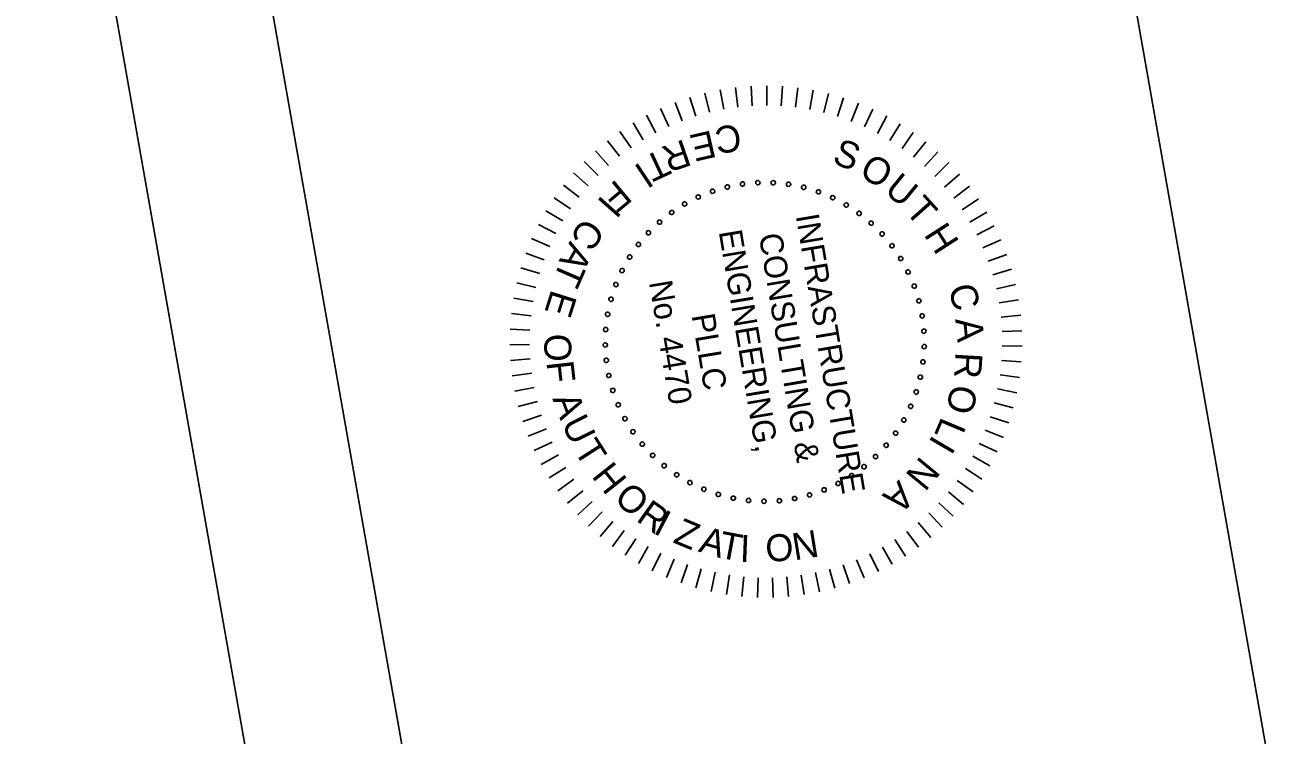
# Model space of a CAD drawing. Extents: x 1971280 to 1971503, y 796034 to 796348.
# Drawn here: x 1971311.8 to 1971344.03, y 796102.52 to 796120.9 of the extents above; entities that cross this region are included whole.
import ezdxf

# ---------------------------------------------------------------- set-up
doc = ezdxf.new("R2010")
doc.units = 0
for name, color, linetype in [('BR_BORDER LINES', 7, 'Continuous'), ('BR_TEXT', 7, 'Continuous'), ('Level 31', 7, 'Continuous')]:
    doc.layers.add(name, color=color, linetype=linetype)

msp = doc.modelspace()

# ---------------------------------------------------------------- linework, layer by layer
at = {"layer": 'BR_BORDER LINES'}
for p, q in [((1971286.058, 796303.806), (1971332.766, 796038.559)), ((1971336.584, 796143.739), (1971344.027, 796101.468))]:
    msp.add_line(p, q, dxfattribs=at)
at = {"layer": 'BR_TEXT'}
for p, q in [((1971330.985, 796119.326), (1971330.985, 796118.816)), ((1971328.996, 796119.026), (1971329.148, 796118.54)), ((1971329.385, 796119.134), (1971329.507, 796118.64)), ((1971329.78, 796119.219), (1971329.872, 796118.718)), ((1971330.179, 796119.279), (1971330.241, 796118.773)), ((1971330.582, 796119.314), (1971330.612, 796118.806)), ((1971331.389, 796119.312), (1971331.357, 796118.804)), ((1971331.791, 796119.274), (1971331.728, 796118.769)), ((1971332.19, 796119.212), (1971332.097, 796118.711)), ((1971332.585, 796119.125), (1971332.461, 796118.631)), ((1971332.973, 796119.014), (1971332.819, 796118.529)), ((1971328.241, 796118.739), (1971328.452, 796118.275)), ((1971328.614, 796118.894), (1971328.796, 796118.418)), ((1971333.354, 796118.88), (1971333.171, 796118.405)), ((1971333.726, 796118.723), (1971333.514, 796118.26)), ((1971327.527, 796118.363), (1971327.792, 796117.928)), ((1971327.879, 796118.562), (1971328.117, 796118.111)), ((1971334.088, 796118.544), (1971333.848, 796118.094)), ((1971327.189, 796118.142), (1971327.48, 796117.724)), ((1971334.438, 796118.342), (1971334.172, 796117.908)), ((1971334.775, 796118.12), (1971334.483, 796117.703)), ((1971326.864, 796117.902), (1971327.18, 796117.503)), ((1971335.099, 796117.878), (1971334.781, 796117.48)), ((1971326.555, 796117.642), (1971326.895, 796117.263)), ((1971335.406, 796117.616), (1971335.065, 796117.238)), ((1971325.987, 796117.069), (1971326.37, 796116.733)), ((1971326.262, 796117.364), (1971326.624, 796117.006)), ((1971335.697, 796117.337), (1971335.334, 796116.98)), ((1971325.73, 796116.757), (1971326.133, 796116.446)), ((1971335.971, 796117.039), (1971335.586, 796116.706)), ((1971325.492, 796116.43), (1971325.914, 796116.144)), ((1971336.226, 796116.726), (1971335.822, 796116.416)), ((1971336.462, 796116.398), (1971336.039, 796116.113)), ((1971325.275, 796116.09), (1971325.713, 796115.83)), ((1971336.677, 796116.056), (1971336.238, 796115.798)), ((1971325.08, 796115.736), (1971325.533, 796115.504)), ((1971336.87, 796115.702), (1971336.416, 796115.471)), ((1971324.906, 796115.372), (1971325.372, 796115.167)), ((1971337.042, 796115.336), (1971336.575, 796115.133)), ((1971324.754, 796114.997), (1971325.232, 796114.822)), ((1971337.191, 796114.961), (1971336.713, 796114.787)), ((1971324.626, 796114.615), (1971325.114, 796114.468)), ((1971337.317, 796114.577), (1971336.829, 796114.433)), ((1971324.521, 796114.224), (1971325.017, 796114.108)), ((1971337.42, 796114.187), (1971336.923, 796114.072)), ((1971324.441, 796113.829), (1971324.943, 796113.743)), ((1971337.498, 796113.79), (1971336.996, 796113.706)), ((1971324.384, 796113.429), (1971324.891, 796113.374)), ((1971337.552, 796113.39), (1971337.046, 796113.337)), ((1971324.352, 796113.026), (1971324.861, 796113.002)), ((1971337.582, 796112.987), (1971337.073, 796112.965)), ((1971324.345, 796112.622), (1971324.854, 796112.629)), ((1971337.587, 796112.584), (1971337.077, 796112.592)), ((1971324.362, 796112.219), (1971324.87, 796112.257)), ((1971337.567, 796112.18), (1971337.059, 796112.22)), ((1971324.404, 796111.817), (1971324.909, 796111.886)), ((1971337.523, 796111.779), (1971337.018, 796111.849)), ((1971324.47, 796111.419), (1971324.97, 796111.518)), ((1971337.454, 796111.381), (1971336.955, 796111.482)), ((1971324.561, 796111.025), (1971325.053, 796111.155)), ((1971337.361, 796110.988), (1971336.869, 796111.119)), ((1971324.675, 796110.638), (1971325.159, 796110.797)), ((1971337.245, 796110.601), (1971336.762, 796110.762)), ((1971324.813, 796110.258), (1971325.286, 796110.447)), ((1971337.105, 796110.222), (1971336.633, 796110.412)), ((1971324.973, 796109.888), (1971325.434, 796110.105)), ((1971336.942, 796109.853), (1971336.482, 796110.071)), ((1971325.156, 796109.527), (1971325.603, 796109.772)), ((1971336.757, 796109.493), (1971336.312, 796109.74)), ((1971325.361, 796109.179), (1971325.791, 796109.451)), ((1971336.551, 796109.146), (1971336.121, 796109.42)), ((1971325.586, 796108.844), (1971325.999, 796109.141)), ((1971336.324, 796108.813), (1971335.911, 796109.111)), ((1971325.831, 796108.523), (1971326.226, 796108.845)), ((1971336.076, 796108.493), (1971335.683, 796108.817)), ((1971326.096, 796108.218), (1971326.47, 796108.563)), ((1971335.81, 796108.189), (1971335.437, 796108.536)), ((1971326.378, 796107.929), (1971326.731, 796108.297)), ((1971326.678, 796107.659), (1971327.007, 796108.047)), ((1971335.526, 796107.903), (1971335.175, 796108.271)), ((1971326.993, 796107.406), (1971327.298, 796107.814)), ((1971334.908, 796107.383), (1971334.604, 796107.792)), ((1971335.225, 796107.633), (1971334.897, 796108.023)), ((1971327.324, 796107.174), (1971327.603, 796107.6)), ((1971327.668, 796106.962), (1971327.921, 796107.404)), ((1971334.576, 796107.153), (1971334.298, 796107.58)), ((1971328.024, 796106.772), (1971328.25, 796107.229)), ((1971333.874, 796106.755), (1971333.649, 796107.212)), ((1971334.231, 796106.943), (1971333.979, 796107.386)), ((1971328.391, 796106.604), (1971328.588, 796107.073)), ((1971328.768, 796106.458), (1971328.936, 796106.939)), ((1971329.152, 796106.336), (1971329.291, 796106.826)), ((1971332.742, 796106.325), (1971332.605, 796106.816)), ((1971333.128, 796106.445), (1971332.961, 796106.926)), ((1971333.506, 796106.589), (1971333.31, 796107.059)), ((1971329.544, 796106.237), (1971329.653, 796106.734)), ((1971329.941, 796106.162), (1971330.019, 796106.665)), ((1971330.342, 796106.112), (1971330.389, 796106.619)), ((1971330.745, 796106.086), (1971330.761, 796106.595)), ((1971331.149, 796106.085), (1971331.134, 796106.594)), ((1971331.552, 796106.108), (1971331.506, 796106.616)), ((1971331.953, 796106.156), (1971331.876, 796106.66)), ((1971332.35, 796106.229), (1971332.243, 796106.727))]:
    msp.add_line(p, q, dxfattribs=at)
for centre, start, end in [((1971329.967, 796116.708), 13.6677, 193.6677), ((1971330.358, 796116.783), 8.1292, 188.1292), ((1971330.358, 796116.783), 188.1292, 8.1292), ((1971330.755, 796116.819), 2.5907, 182.5907), ((1971330.755, 796116.819), 182.5907, 2.5907), ((1971331.154, 796116.817), 357.0523, 177.0523), ((1971331.154, 796116.817), 177.0523, 357.0523), ((1971331.55, 796116.776), 171.5138, 351.5138), ((1971331.55, 796116.776), 351.5138, 171.5138), ((1971331.941, 796116.698), 345.9753, 165.9753), ((1971329.214, 796116.447), 24.7446, 204.7446), ((1971329.214, 796116.447), 204.7446, 24.7446), ((1971329.584, 796116.596), 19.2061, 199.2061), ((1971329.584, 796116.596), 199.2061, 19.2061), ((1971329.967, 796116.708), 193.6677, 13.6677), ((1971331.941, 796116.698), 165.9753, 345.9753), ((1971332.323, 796116.582), 160.4369, 340.4369), ((1971332.323, 796116.582), 340.4369, 160.4369), ((1971332.691, 796116.43), 154.8984, 334.8984), ((1971332.691, 796116.43), 334.8984, 154.8984), ((1971328.526, 796116.047), 35.8215, 215.8215), ((1971328.86, 796116.264), 30.283, 210.283), ((1971328.86, 796116.264), 210.283, 30.283), ((1971333.043, 796116.243), 149.36, 329.36), ((1971333.043, 796116.243), 329.36, 149.36), ((1971328.214, 796115.799), 41.36, 221.36), ((1971328.214, 796115.799), 221.36, 41.36), ((1971328.526, 796116.047), 215.8215, 35.8215), ((1971333.375, 796116.022), 143.8215, 323.8215), ((1971333.375, 796116.022), 323.8215, 143.8215), ((1971333.685, 796115.771), 138.283, 318.283), ((1971333.685, 796115.771), 318.283, 138.283), ((1971327.927, 796115.522), 46.8984, 226.8984), ((1971327.927, 796115.522), 226.8984, 46.8984), ((1971333.969, 796115.491), 132.7446, 312.7446), ((1971333.969, 796115.491), 312.7446, 132.7446), ((1971327.668, 796115.219), 52.4369, 232.4369), ((1971327.668, 796115.219), 232.4369, 52.4369), ((1971334.224, 796115.185), 127.2061, 307.2061), ((1971334.224, 796115.185), 307.2061, 127.2061), ((1971327.44, 796114.892), 57.9753, 237.9753), ((1971327.44, 796114.892), 237.9753, 57.9753), ((1971334.449, 796114.856), 121.6677, 301.6677), ((1971334.449, 796114.856), 301.6677, 121.6677), ((1971327.245, 796114.544), 63.5138, 243.5138), ((1971327.245, 796114.544), 243.5138, 63.5138), ((1971334.641, 796114.507), 116.1292, 296.1292), ((1971334.641, 796114.507), 296.1292, 116.1292), ((1971327.084, 796114.18), 69.0523, 249.0523), ((1971327.084, 796114.18), 249.0523, 69.0523), ((1971334.798, 796114.14), 110.5907, 290.5907), ((1971334.798, 796114.14), 290.5907, 110.5907), ((1971326.958, 796113.801), 74.5907, 254.5907), ((1971326.958, 796113.801), 254.5907, 74.5907), ((1971334.92, 796113.761), 105.0523, 285.0523), ((1971334.92, 796113.761), 285.0523, 105.0523), ((1971326.87, 796113.412), 80.1292, 260.1292), ((1971326.87, 796113.412), 260.1292, 80.1292), ((1971335.004, 796113.371), 99.5138, 279.5138), ((1971335.004, 796113.371), 279.5138, 99.5138), ((1971326.82, 796113.017), 85.6677, 265.6677), ((1971326.82, 796113.017), 265.6677, 85.6677), ((1971335.05, 796112.975), 93.9753, 273.9753), ((1971335.05, 796112.975), 273.9753, 93.9753), ((1971326.809, 796112.619), 91.2061, 271.2061), ((1971326.809, 796112.619), 271.2061, 91.2061), ((1971335.057, 796112.576), 88.4369, 268.4369), ((1971335.057, 796112.576), 268.4369, 88.4369), ((1971326.836, 796112.221), 96.7446, 276.7446), ((1971326.836, 796112.221), 276.7446, 96.7446), ((1971335.026, 796112.179), 82.8984, 262.8984), ((1971335.026, 796112.179), 262.8984, 82.8984), ((1971326.901, 796111.827), 102.283, 282.283), ((1971326.901, 796111.827), 282.283, 102.283), ((1971334.957, 796111.786), 77.36, 257.36), ((1971334.957, 796111.786), 257.36, 77.36), ((1971327.003, 796111.442), 107.8215, 287.8215), ((1971327.003, 796111.442), 287.8215, 107.8215), ((1971334.851, 796111.402), 71.8215, 251.8215), ((1971334.851, 796111.402), 251.8215, 71.8215), ((1971327.143, 796111.069), 113.36, 293.36), ((1971327.143, 796111.069), 293.36, 113.36), ((1971334.707, 796111.03), 66.283, 246.283), ((1971334.707, 796111.03), 246.283, 66.283), ((1971327.318, 796110.711), 118.8984, 298.8984), ((1971327.318, 796110.711), 298.8984, 118.8984), ((1971334.529, 796110.674), 60.7446, 240.7446), ((1971334.529, 796110.674), 240.7446, 60.7446), ((1971327.526, 796110.371), 124.4369, 304.4369), ((1971327.526, 796110.371), 304.4369, 124.4369), ((1971334.317, 796110.336), 55.2061, 235.2061), ((1971334.317, 796110.336), 235.2061, 55.2061), ((1971327.767, 796110.053), 129.9753, 309.9753), ((1971327.767, 796110.053), 309.9753, 129.9753), ((1971334.073, 796110.021), 49.6677, 229.6677), ((1971334.073, 796110.021), 229.6677, 49.6677), ((1971328.037, 796109.76), 135.5138, 315.5138), ((1971328.037, 796109.76), 315.5138, 135.5138), ((1971333.8, 796109.73), 44.1292, 224.1292), ((1971333.8, 796109.73), 224.1292, 44.1292), ((1971328.334, 796109.494), 141.0523, 321.0523), ((1971328.334, 796109.494), 321.0523, 141.0523), ((1971333.5, 796109.467), 38.5907, 218.5907), ((1971333.5, 796109.467), 218.5907, 38.5907), ((1971328.655, 796109.258), 146.5907, 326.5907), ((1971328.655, 796109.258), 326.5907, 146.5907), ((1971328.998, 796109.054), 152.1292, 332.1292), ((1971328.998, 796109.054), 332.1292, 152.1292), ((1971332.832, 796109.034), 27.5138, 207.5138), ((1971332.832, 796109.034), 207.5138, 27.5138), ((1971333.177, 796109.235), 33.0523, 213.0523), ((1971333.177, 796109.235), 213.0523, 33.0523), ((1971329.358, 796108.884), 157.6677, 337.6677), ((1971329.358, 796108.884), 337.6677, 157.6677), ((1971329.734, 796108.75), 163.2061, 343.2061), ((1971329.734, 796108.75), 343.2061, 163.2061), ((1971330.12, 796108.653), 348.7446, 168.7446), ((1971331.706, 796108.644), 10.8984, 190.8984), ((1971332.093, 796108.738), 16.4369, 196.4369), ((1971332.093, 796108.738), 196.4369, 16.4369), ((1971332.47, 796108.868), 21.9753, 201.9753), ((1971332.47, 796108.868), 201.9753, 21.9753), ((1971330.12, 796108.653), 168.7446, 348.7446), ((1971330.514, 796108.593), 174.283, 354.283), ((1971330.514, 796108.593), 354.283, 174.283), ((1971330.912, 796108.572), 359.8215, 179.8215), ((1971330.912, 796108.572), 179.8215, 359.8215), ((1971331.311, 796108.589), 5.36, 185.36), ((1971331.311, 796108.589), 185.36, 5.36), ((1971331.706, 796108.644), 190.8984, 10.8984)]:
    msp.add_arc(centre, 0.0561, start, end, dxfattribs=at)
at = {"layer": 'Level 31'}
msp.add_line((1971279.575, 796317.557), (1971329.522, 796033.921), dxfattribs=at)

# ---------------------------------------------------------------- texts
at = {"layer": 'BR_TEXT'}
for s, height, rotation, p in [('E', 0.698, 193.012, (1971329.565, 796118.177)), ('C', 0.698, 187.012, (1971330.281, 796118.338)), ('R', 0.698, 199.012, (1971328.856, 796117.948)), ('S', 0.698, 338.8952, (1971332.65, 796117.334)), ('T', 0.698, 205.012, (1971328.26, 796117.702)), ('O', 0.698, 329.8652, (1971333.343, 796117.006)), ('I', 0.698, 213.7582, (1971327.725, 796117.366)), ('U', 0.698, 320.8352, (1971333.996, 796116.577)), ('F', 0.698, 219.7582, (1971327.104, 796116.922)), ('I', 0.698, 228.5138, (1971326.738, 796116.516)), ('T', 0.698, 311.8052, (1971334.539, 796116.077)), ('C', 0.698, 234.5138, (1971326.268, 796115.951)), ('INFRASTRUCTURE', 0.59817, 279.5138, (1971331.734, 796115.965)), ('H', 0.698, 302.7751, (1971335.033, 796115.475)), ('ENGINEERING,', 0.59817, 279.5138, (1971329.743, 796115.552)), ('CONSULTING &', 0.59817, 279.5138, (1971330.778, 796115.462)), ('A', 0.698, 240.5138, (1971325.902, 796115.325)), ('T', 0.698, 246.5138, (1971325.675, 796114.842)), ('No. 4470', 0.5982, 279.5138, (1971327.939, 796114.242)), ('C', 0.698, 284.7151, (1971335.676, 796114.103)), ('E', 0.698, 252.5138, (1971325.421, 796114.078)), ('PLLC', 0.5982, 279.5138, (1971329.04, 796113.384)), ('A', 0.698, 275.6851, (1971335.859, 796113.286)), ('O', 0.698, 270.5138, (1971325.231, 796112.906)), ('R', 0.698, 266.655, (1971335.87, 796112.441)), ('F', 0.698, 276.5138, (1971325.285, 796112.173)), ('O', 0.698, 257.625, (1971335.771, 796111.63)), ('A', 0.698, 290.5138, (1971325.439, 796111.226)), ('U', 0.698, 296.5138, (1971325.662, 796110.584)), ('L', 0.698, 247.095, (1971335.511, 796110.781)), ('T', 0.698, 302.5138, (1971325.981, 796109.895)), ('I', 0.698, 239.565, (1971335.286, 796110.315)), ('N', 0.698, 230.5349, (1971334.97, 796109.765)), ('H', 0.698, 308.5138, (1971326.439, 796109.219)), ('A', 0.698, 221.5049, (1971334.411, 796109.138)), ('O', 0.698, 318.5138, (1971327.003, 796108.602)), ('R', 0.698, 324.5138, (1971327.581, 796108.082)), ('I', 0.698, 332.3209, (1971328.023, 796107.759)), ('Z', 0.698, 337.3824, (1971328.534, 796107.515)), ('A', 0.698, 343.3824, (1971329.196, 796107.276)), ('T', 0.698, 349.3824, (1971329.714, 796107.117)), ('O', 0.698, 3.1955, (1971330.968, 796107.003)), ('N', 0.698, 9.1955, (1971331.703, 796107.042)), ('I', 0.698, 357.8962, (1971330.282, 796107.008))]:
    msp.add_text(s, height=height, rotation=rotation, dxfattribs=at).set_placement(p)

doc.saveas('drawing.dxf')
